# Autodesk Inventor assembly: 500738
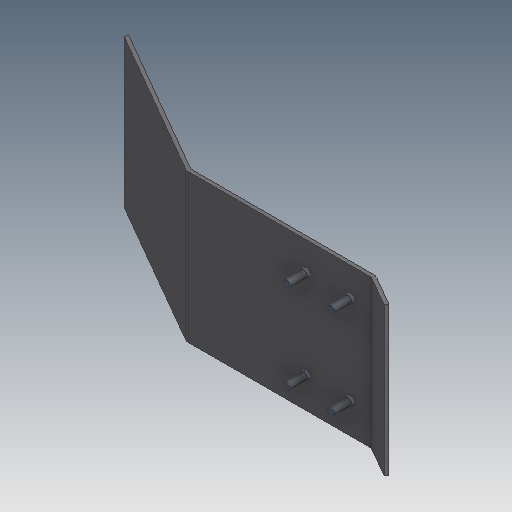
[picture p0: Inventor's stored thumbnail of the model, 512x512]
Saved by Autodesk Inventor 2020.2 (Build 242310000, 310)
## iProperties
Created: 2000-03
Part Number: 500738
Document SubType Name: Assembly
Designer: sspink
Mass: 149.717 g
Surface Area: 900.885 cm^2
Volume: 129.563 cm^3
Density: 1.15555 g/cm^3
Control State: 0
Master: False
Checked Out: False
Shininess: 0.0
Length Units: 11272
Angle Units: 11279
Time Units: 11290
Mass Units: 11286
Length Display Precision: 3
Angle Display Precision: 2
Compacted: True
Dimensions: 5x3,6x12,3 in
Mass: 0,33 lb
DocNumber: 500738.iam
Folder: 01 - Themengebiete\Simplification\01 - Packaging machine\
VDS_Category: 3D Komponenten
Density: 0.0
Volumn: 0.0
Area: 0.0
PropertySet Name: Model Information
Author: sspink
Revision Number: -
Title: 500738
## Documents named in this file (3)
- D:\07 - DEMODATEN\OTX 2019 - Dataset - UPDATE - Dez2019\Designs\07-Packing machine\500738.iam
- D:\07 - DEMODATEN\OTX 2019 - Dataset - UPDATE - Dez2019\Designs\07-Packing machine\Parts\ADSK-011748.ipt
- D:\07 - DEMODATEN\OTX 2019 - Dataset - UPDATE - Dez2019\Designs\07-Packing machine\Parts\ADSK-011696.ipt
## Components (5 placed, 2 different names)
1. ADSK-011696:1 — Mate:1, Flush:1, Mate:2, Flush:2, Mate:3, Flush:3, Mate:4, Flush:4
2. ADSK-011748:1 — Mate:2, Flush:2
3. ADSK-011748:2 — Mate:4, Flush:4
4. ADSK-011748:3 — Mate:3, Flush:3
5. ADSK-011748:4 — Mate:1, Flush:1
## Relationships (8: Mate 4, Flush 4)
- Mate:1: ADSK-011696:1 ↔ ADSK-011748:4
- Flush:1: ADSK-011696:1 ↔ ADSK-011748:4
- Mate:2: ADSK-011696:1 ↔ ADSK-011748:1
- Flush:2: ADSK-011696:1 ↔ ADSK-011748:1
- Mate:3: ADSK-011696:1 ↔ ADSK-011748:3
- Flush:3: ADSK-011696:1 ↔ ADSK-011748:3
- Mate:4: ADSK-011696:1 ↔ ADSK-011748:2
- Flush:4: ADSK-011696:1 ↔ ADSK-011748:2
